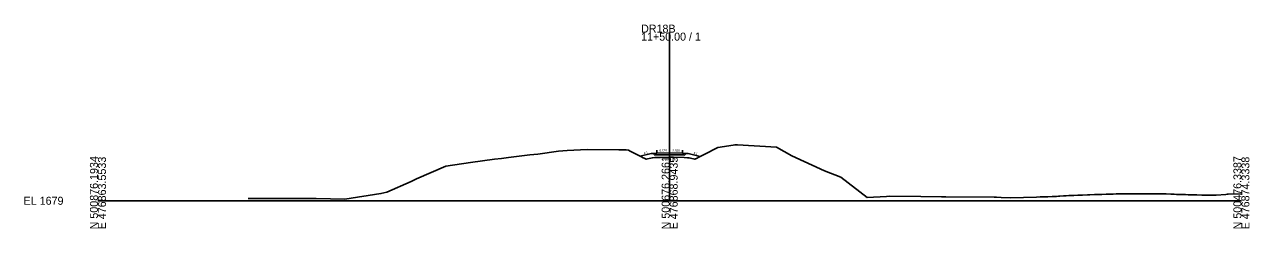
# Model space of a CAD drawing. Extents: x -26 to 403, y -10 to 2578.
# Drawn here: x -25.7 to 402.8, y 1490.3 to 1561.6 of the extents above; entities that cross this region are included whole.
import ezdxf

# ---------------------------------------------------------------- set-up
doc = ezdxf.new("R2010")
doc.units = 0
for name, color, linetype in [('Exist Cross Section Cell', 7, 'Continuous'), ('Exist XS Center Line Elevation Label', 7, 'Continuous'), ('Exist XS Ground Line', 7, 'Continuous'), ('Prop XS Ditch Slope Text', 7, 'Continuous'), ('Prop XS Earthwork Shape', 7, 'Continuous'), ('Prop XS EOT Tick Mark', 7, 'Continuous'), ('Prop XS Finish Grade', 7, 'Continuous'), ('Prop XS Finish Grade Earthwork', 7, 'Continuous'), ('Prop XS Finish Grade Pavement', 7, 'Continuous'), ('Prop XS Hydro Typical Ditch Data', 7, 'Continuous'), ('Prop XS Pvmt Edge Slope', 7, 'Continuous'), ('Prop XS SE Text', 7, 'Continuous'), ('Prop XS Shoulder Borrow Shape', 7, 'Continuous'), ('Prop XS Subgrade Earthwork', 7, 'Continuous')]:
    doc.layers.add(name, color=color, linetype=linetype)

msp = doc.modelspace()

# ---------------------------------------------------------------- linework, layer by layer
at = {"layer": 'Exist Cross Section Cell'}
for p, q in [((200, 1500), (200, 1558.79)), ((0, 1500), (200, 1500)), ((200, 1500), (400, 1500))]:
    msp.add_line(p, q, dxfattribs=at)
at = {"layer": 'Exist XS Ground Line'}
msp.add_lwpolyline([(52.56, 1500.85), (55.51, 1500.83), (59.26, 1500.75), (76.39, 1500.84), (86.36, 1500.52), (98.97, 1502.49), (101.11, 1503.01), (109.52, 1506.74), (111.41, 1507.65), (121.66, 1512.07), (130.36, 1513.36), (138.75, 1514.53), (141.13, 1514.82), (143.64, 1515.14), (151.13, 1516.04), (153.92, 1516.33), (161.14, 1517.35), (164.2, 1517.55), (171.14, 1517.91), (182.23, 1517.83), (184.77, 1517.83), (185.56, 1517.65), (186.21, 1517.29), (187.15, 1516.83), (189.92, 1515.46), (190.72, 1515.06), (191.1, 1514.87), (191.81, 1514.51), (192.25, 1514.62), (193.97, 1515.03), (194.83, 1515.09), (195.8, 1515.18), (196.81, 1515.18), (200, 1515.26), (200.3, 1515.27), (201.31, 1515.24), (205.08, 1515.16), (206.23, 1515.07), (206.8, 1515.02), (207.25, 1514.91), (208.8, 1514.52), (209.62, 1514.93), (209.93, 1515.09), (212.03, 1516.14), (216.83, 1518.57), (217.64, 1518.72), (222.86, 1519.6), (223.77, 1519.53), (237.38, 1518.7), (242.78, 1515.71), (254.21, 1510.52), (259.85, 1508.23), (269.14, 1501.09), (275.89, 1501.5), (276.95, 1501.56), (287.91, 1501.45), (295.08, 1501.38), (295.77, 1501.39), (296.62, 1501.37), (313.49, 1501.26), (314.35, 1501.21), (315.95, 1501.15), (319.19, 1501.08), (323.82, 1501.11), (328.27, 1501.29), (329.59, 1501.33), (332.28, 1501.37), (333.86, 1501.46), (335.33, 1501.5), (336.07, 1501.59), (336.51, 1501.63), (337.77, 1501.71), (338.71, 1501.78), (339.61, 1501.82), (340.45, 1501.87), (340.87, 1501.88), (341.4, 1501.9), (342.81, 1501.94), (343.64, 1501.97), (344.38, 1501.99), (346.21, 1502.06), (347.04, 1502.09), (348.66, 1502.14), (349.58, 1502.17), (351.14, 1502.22), (352.68, 1502.28), (353.68, 1502.32), (355.15, 1502.36), (356.18, 1502.41), (357.56, 1502.4), (358.64, 1502.43), (359.98, 1502.43), (361.12, 1502.44), (362.33, 1502.44), (363.62, 1502.44), (364.92, 1502.44), (366.14, 1502.44), (367.53, 1502.43), (368.9, 1502.44), (370.74, 1502.44), (371.29, 1502.42), (373.69, 1502.37), (375.3, 1502.31), (376.53, 1502.26), (377.31, 1502.23), (378.68, 1502.2), (380.41, 1502.15), (381.41, 1502.13), (382.1, 1502.12), (382.51, 1502.1), (383.72, 1502.04), (384.38, 1502.02), (386.17, 1501.95), (386.8, 1501.94), (388.67, 1501.91), (389.64, 1501.92), (390.74, 1501.93), (391.15, 1501.95), (394.58, 1502.21), (395.03, 1502.26), (395.39, 1502.28), (400, 1502.39)], dxfattribs=at)
at = {"layer": 'Prop XS Earthwork Shape'}
msp.add_lwpolyline([(200, 1516.1), (195.5, 1516.01), (194.82, 1516), (194.24, 1516.58), (193.5, 1516.52), (189.69, 1515.57), (189.92, 1515.46), (190.72, 1515.06), (191.1, 1514.87), (191.81, 1514.51), (192.25, 1514.62), (193.97, 1515.03), (194.83, 1515.09), (195.8, 1515.18), (196.81, 1515.18), (200, 1515.26), (200.3, 1515.27), (201.31, 1515.24), (205.08, 1515.16), (206.23, 1515.07), (206.8, 1515.02), (207.25, 1514.91), (208.8, 1514.52), (209.62, 1514.93), (209.93, 1515.09), (210.69, 1515.47), (206.5, 1516.52), (205.76, 1516.58), (205.18, 1516), (204.5, 1516.01)], close=True, dxfattribs=at)
at = {"layer": 'Prop XS EOT Tick Mark'}
for p, q in [((195.5, 1516.68), (195.5, 1517.68)), ((204.5, 1516.68), (204.5, 1517.68))]:
    msp.add_line(p, q, dxfattribs=at)
at = {"layer": 'Prop XS Finish Grade'}
for p, q in [((195.5, 1516.68), (194.24, 1516.58)), ((204.5, 1516.68), (205.76, 1516.58))]:
    msp.add_line(p, q, dxfattribs=at)
at = {"layer": 'Prop XS Finish Grade Earthwork'}
for p, q in [((193.5, 1516.52), (189.69, 1515.57)), ((194.24, 1516.58), (193.5, 1516.52)), ((205.76, 1516.58), (206.5, 1516.52)), ((206.5, 1516.52), (210.69, 1515.47))]:
    msp.add_line(p, q, dxfattribs=at)
at = {"layer": 'Prop XS Finish Grade Pavement'}
for p, q in [((195.5, 1516.68), (200, 1516.77)), ((200, 1516.77), (204.5, 1516.68))]:
    msp.add_line(p, q, dxfattribs=at)
at = {"layer": 'Prop XS Hydro Typical Ditch Data'}
msp.add_line((193.5, 1516.52), (189.69, 1515.57), dxfattribs=at)
at = {"layer": 'Prop XS Pvmt Edge Slope'}
for p, q in [((195.5, 1516.68), (194.82, 1516)), ((204.5, 1516.68), (205.18, 1516))]:
    msp.add_line(p, q, dxfattribs=at)
at = {"layer": 'Prop XS Shoulder Borrow Shape'}
for points in [[(195.5, 1516.68), (194.24, 1516.58), (194.82, 1516)], [(204.5, 1516.68), (205.76, 1516.58), (205.18, 1516)]]:
    msp.add_lwpolyline(points, close=True, dxfattribs=at)
at = {"layer": 'Prop XS Subgrade Earthwork'}
for p, q in [((194.82, 1516), (194.24, 1516.58)), ((195.5, 1516.01), (194.82, 1516)), ((200, 1516.1), (195.5, 1516.01)), ((204.5, 1516.01), (200, 1516.1)), ((204.5, 1516.01), (205.18, 1516)), ((205.18, 1516), (205.76, 1516.58))]:
    msp.add_line(p, q, dxfattribs=at)

# ---------------------------------------------------------------- texts
at = {"layer": 'Exist Cross Section Cell'}
for s, p in [('DR18B', (190, 1558.79)), ('11+50.00 / 1', (190, 1555.99)), ('EL 1679', (-26, 1498.6))]:
    msp.add_text(s, height=2.8, dxfattribs=at).set_placement(p)
for s, p in [('N 500876.1934', (0, 1490)), ('E 476863.5533', (2.8, 1490)), ('N 500676.2661', (200, 1490)), ('E 476868.9435', (202.8, 1490)), ('N 500476.3387', (400, 1490)), ('E 476874.3338', (402.8, 1490))]:
    msp.add_text(s, height=2.8, rotation=90, dxfattribs=at).set_placement(p)
at = {"layer": 'Exist XS Center Line Elevation Label'}
msp.add_text('1694.26', height=0.75, dxfattribs=at).set_placement((198.26, 1514.08))
at = {"layer": 'Prop XS Ditch Slope Text'}
for rotation, p in [(14.0362, (191.01, 1516.27)), (345.9638, (208.29, 1516.42))]:
    msp.add_text('4:1', height=0.75, rotation=rotation, dxfattribs=at).set_placement(p)
at = {"layer": 'Prop XS SE Text'}
for rotation, p in [(1.1458, (196.44, 1517.2)), (358.8542, (200.94, 1517.25))]:
    msp.add_text('0.020', height=0.75, rotation=rotation, dxfattribs=at).set_placement(p)

doc.saveas('drawing.dxf')
